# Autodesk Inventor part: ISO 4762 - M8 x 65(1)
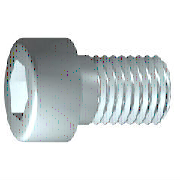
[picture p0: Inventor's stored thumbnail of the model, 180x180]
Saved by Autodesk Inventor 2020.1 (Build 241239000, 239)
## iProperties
Created: 2019-01
Part Number: ISO 4762 - M8 x 65(1)
Material: Edelstahl, 440C
Description: Innensechskantschraube
Document SubType Name: Modeling
Standard: ISO 4762
Designer: lutzd
Standard Revision: Fourth edition 2004-03-01
Standards Organization: ISO
Language: de-DE
Size Designation: M8 x 65
Categories: <MemberInstance><Categories><Category DisplayName="Verbindungselemente" InternalName="e4da775c-781d-43d5-af7c-5136215cf5a6" Mnemonic="FSTN"><Category DisplayNam
Mass: 32.2993 g
Surface Area: 22.9 cm^2
Volume: 4.16765 cm^3
Density: 7.75 g/cm^3
Appearance: Halbpoliert
IsCustomPart: 0
Author: lutzd
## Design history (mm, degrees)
workplane "Work Plane1"
fillet "Fillet2" dims "d30" = 0.1 (= R)
sketch "Skizze1"
  geometry: L1 (-2, 0)-(65, 0); L2 (65, 0)-(65, 4); L3 (65, 4)-(37, 4); L4 (37, 4)-(36.233, 4); L5 (36.233, 4)-(0, 4); L6 (0, 4)-(0, 6.5); L7 (0, 6.5)-(-8, 6.5); L8 (-8, 6.5)-(-8, 3.464); L9 (-8, 3.464)-(-4, 3.464); L10 (-4, 3.464)-(-2, 0); L11 (-22.6, 0)-(79.6, 0) reference; L12 (0, -1.3)-(0, 7.8) reference; L13 (37, 4)-(0, 4)
  constraints: 22 end point, 6 parallel, 2 collinear, 2 perpendicular, 1 horizontal, 1 point on line
  dimensions: "d1" = 28 distance from line of L3.end L2 (= GEL); "d2" = 0.76691 distance of L4.end L3.end (computed from GAL); "d3" = 8 distance between parallel lines of L8 L6 (= KOH); "d4" = 4 distance of L8.end L9.end (= INTI); "d5" = 60 deg angle of L10 L1; "d6" = 8 diameter of L3 L1 (= GD); "d7" = 8 diameter of L5 L1 (= BDM); "d8" = 6.9282 diameter of L9 L1 (= 1.1547 x SW); "d9" = 13 diameter of L7 L1 (= KOD); "d26" = 65 distance between parallel lines of L12 L2 (= NLG)
revolve "Körper" sketch "Skizze1" stored, may be unused: angle "d10" = 90 deg
sketch "Skizze2"
  geometry: L1 (0, -9.1)-(0, 9.1) reference; L2 (-9.1, 0)-(9.1, 0) reference; L3 (3.464, 0)-(1.732, -3); L4 (1.732, -3)-(-1.732, -3); L5 (-1.732, -3)-(-3.464, 0); L6 (-3.464, 0)-(-1.732, 3); L7 (-1.732, 3)-(1.732, 3); L8 (1.732, 3)-(3.464, 0); 2 further points
  constraints: 12 end point, 1 coincident, 1 horizontal alignment, 1 point on line, 12 other
extrude "Loch" join sketch "Skizze2" stored distance "d11" = 10; taper "d12" = 0 deg
body "Solid1"
fillet "Rundung1" dims "d17" = 0.8 (= RR)
feature "Gewinde" dims "d13" = 28 (= GEL), "d14" = 0
chamfer "Fase1" distance "d15" = 0.76681 (= -0.5 x SPD + 0.5 x GD); stored, may be unused: second distance "d16" = 0.76681 (= GUL), angle "d27" = 45 deg
other parameters: "GD" = 8 [user parameter; used in 2 equation terms], "NLG" = 65 [user parameter; used in 1 equation term], "GEL" = 28 [user parameter; used in 2 equation terms], "KOD" = 13 [user parameter; used in 1 equation term], "KOH" = 8 [user parameter; used in 1 equation term], "INTI" = 4 [user parameter; used in 1 equation term], "GAL" = 0.76681 (= 0.61345 x PTC) [user parameter; used in 1 equation term], "GUL" = 0.76681 (= 0.61345 x PTC) [user parameter; used in 1 equation term], "BDM" = 8 (= NND) [user parameter; used in 1 equation term], "SW" = 6 [user parameter; used in 2 equation terms], "RR" = 0.8 [user parameter; used in 1 equation term], "SPD" = 6.46637 (= NND - 1.2269 x PTC) [user parameter; used in 1 equation term], "d19" = 0, "d28" = 0, "d29" = 0, "R" = 0.1 [user parameter; used in 1 equation term], "TOA" = 30 deg [user parameter], "GD1" = 6.46637 (= THREADDIA - 1.2269 x PTC) [user parameter], "THREADDIA" = 8 [user parameter; used in 1 equation term], "FAWI" = 45 deg [user parameter], "TPU" = 8 (computed from PTC) [user parameter], "PTC" = 1.25 [user parameter; used in 5 equation terms], "NND" = 8 [user parameter; used in 2 equation terms], "E0" = 6.93 (= 1.155 x SW) [user parameter]
